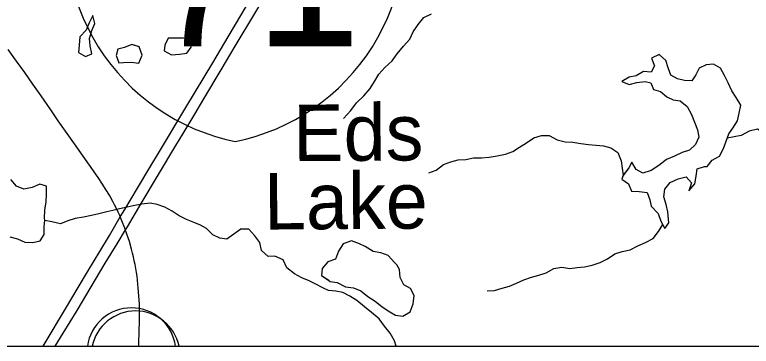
# Model space of a CAD drawing. Extents: x 0 to 34, y 0 to 22.
# Drawn here: x 5.585 to 6.202, y 14.1 to 14.378 of the extents above; entities that cross this region are included whole.
import ezdxf

# ---------------------------------------------------------------- set-up
doc = ezdxf.new("R2010")
doc.units = 0
for name, color, linetype in [('GM_X_Interstate_Route', 7, 'Continuous'), ('GM_X_Interstate_Shield', 7, 'Continuous'), ('GM_X_Minor_Lake', 7, 'Continuous'), ('GM_X_Minor_Lake_Text', 7, 'Continuous'), ('GM_X_Minor_River', 7, 'Continuous'), ('GM_X_Rail_Line_Text', 7, 'Continuous'), ('GM_X_State_Route', 7, 'Continuous'), ('GM_X_Unincorporated_Location', 7, 'Continuous'), ('SH_Cut_Line', 7, 'Continuous'), ('SH_Data', 7, 'Continuous')]:
    doc.layers.add(name, color=color, linetype=linetype)

msp = doc.modelspace()

# ---------------------------------------------------------------- linework, layer by layer
at = {"layer": 'GM_X_Interstate_Route'}
for points in [[(5.67798, 14.19854), (5.67906, 14.20032), (5.69065, 14.21987), (5.71973, 14.26847), (5.72596, 14.27855), (5.73562, 14.29475), (5.7432, 14.30742), (5.75774, 14.33192), (5.76957, 14.35166), (5.80249, 14.40669), (5.808, 14.41604), (5.84195, 14.47264), (5.85026, 14.48655), (5.86397, 14.5094), (5.86958, 14.51854), (5.8945, 14.56039), (5.90385, 14.57596), (5.923, 14.60926), (5.9241, 14.61096)], [(5.60839, 14.1), (5.60927, 14.10147), (5.6281, 14.13291), (5.63695, 14.14778), (5.64664, 14.16387), (5.65605, 14.17956), (5.66403, 14.19295), (5.67316, 14.20845), (5.67689, 14.21479), (5.68766, 14.23262), (5.69708, 14.24845), (5.70698, 14.26485), (5.72812, 14.30025), (5.75058, 14.33766), (5.75982, 14.35336), (5.77875, 14.38497)], [(5.61864, 14.1), (5.6254, 14.111), (5.63703, 14.13011), (5.66057, 14.16971), (5.6704, 14.18605), (5.67744, 14.19766), (5.67798, 14.19854)]]:
    msp.add_lwpolyline(points, dxfattribs=at)
at = {"layer": 'GM_X_Interstate_Shield'}
for centre, start, end in [((5.80508, 14.44572), 165.80665, 258.46304), ((5.73406, 14.44572), 281.53696, 14.19335)]:
    msp.add_arc(centre, 0.17756, start, end, dxfattribs=at)
at = {"layer": 'GM_X_Minor_Lake'}
for points in [[(5.65015, 14.37749), (5.647, 14.37138), (5.64461, 14.36528), (5.63918, 14.35952), (5.63869, 14.35268), (5.6382, 14.34642)], [(5.6382, 14.34642), (5.64412, 14.34307), (5.6494, 14.34542), (5.648, 14.35204), (5.64735, 14.3581), (5.64936, 14.36496), (5.65194, 14.37087), (5.65005, 14.37738)], [(5.6382, 14.34642), (5.64412, 14.34307), (5.6494, 14.34542), (5.648, 14.35204), (5.64735, 14.3581), (5.64936, 14.36496), (5.65194, 14.37087), (5.65007, 14.37733)], [(5.65007, 14.37733), (5.647, 14.37138), (5.64461, 14.36528), (5.63918, 14.35952), (5.63869, 14.35268), (5.6382, 14.34642)], [(5.68905, 14.35108), (5.68289, 14.35305), (5.67666, 14.3505), (5.67098, 14.34929), (5.66972, 14.34397), (5.67188, 14.33773)], [(5.68917, 14.35104), (5.68289, 14.35305), (5.67666, 14.3505), (5.67098, 14.34929), (5.66972, 14.34397), (5.67188, 14.33773)], [(5.73211, 14.3571), (5.72607, 14.35834), (5.71962, 14.35844), (5.71336, 14.35837), (5.7104, 14.35264), (5.70989, 14.34789)], [(5.73216, 14.35709), (5.72607, 14.35834), (5.71962, 14.35844), (5.71336, 14.35837), (5.7104, 14.35264), (5.70989, 14.34789)], [(5.70989, 14.34789), (5.716, 14.34455), (5.72282, 14.34502), (5.72888, 14.34585), (5.73261, 14.35102), (5.73211, 14.3571)], [(5.70989, 14.34789), (5.716, 14.34455), (5.72282, 14.34502), (5.72888, 14.34585), (5.73261, 14.35102), (5.73212, 14.35702)], [(5.67188, 14.33773), (5.67586, 14.33797), (5.68231, 14.33824), (5.68877, 14.33757), (5.69153, 14.34424), (5.68901, 14.35117)], [(5.67188, 14.33773), (5.67586, 14.33797), (5.68231, 14.33824), (5.68877, 14.33757), (5.69153, 14.34424), (5.68905, 14.35108)], [(6.16277, 14.25079), (6.16504, 14.2508), (6.16918, 14.25613), (6.17542, 14.25957), (6.17861, 14.26584), (6.18085, 14.27191), (6.18329, 14.27818), (6.18649, 14.28293), (6.19044, 14.28902), (6.19193, 14.29547), (6.19323, 14.3023), (6.18941, 14.30854), (6.18579, 14.31421), (6.18274, 14.32084), (6.17949, 14.32708), (6.17625, 14.33332), (6.17037, 14.33652), (6.16431, 14.33611), (6.15826, 14.33324), (6.15545, 14.32754), (6.15206, 14.32278), (6.146, 14.32295), (6.14013, 14.32425), (6.13444, 14.32726), (6.13233, 14.3335), (6.13041, 14.33975), (6.12471, 14.34485), (6.11847, 14.34179), (6.12077, 14.33535), (6.11814, 14.32984), (6.11171, 14.33038), (6.10547, 14.32694), (6.09961, 14.32559), (6.09338, 14.32196), (6.09963, 14.31952), (6.10606, 14.32126), (6.11306, 14.32204), (6.1178, 14.32093), (6.1201, 14.31525), (6.12578, 14.31357), (6.1311, 14.30923), (6.13641, 14.3066), (6.14247, 14.30587), (6.14817, 14.30116), (6.1518, 14.29454), (6.15447, 14.2881), (6.15696, 14.28148), (6.15812, 14.27542), (6.15512, 14.26915), (6.15022, 14.26439), (6.14398, 14.26265), (6.13755, 14.25959), (6.13094, 14.25672), (6.12452, 14.25176), (6.1181, 14.24737), (6.11111, 14.24525), (6.10561, 14.24826), (6.10179, 14.25431), (6.09935, 14.24956), (6.09474, 14.24339)], [(6.16277, 14.25079), (6.16504, 14.2508), (6.16918, 14.25613), (6.17542, 14.25957), (6.17861, 14.26584), (6.18085, 14.27191), (6.18329, 14.27818), (6.18649, 14.28293), (6.19044, 14.28902), (6.19193, 14.29547), (6.19323, 14.3023), (6.18941, 14.30854), (6.18579, 14.31421), (6.18274, 14.32084), (6.17949, 14.32708), (6.17625, 14.33332), (6.17037, 14.33652), (6.16431, 14.33611), (6.15826, 14.33324), (6.15545, 14.32754), (6.15206, 14.32278), (6.146, 14.32295), (6.14013, 14.32425), (6.13444, 14.32726), (6.13233, 14.3335), (6.13041, 14.33975), (6.12471, 14.34485), (6.11847, 14.34179), (6.12077, 14.33535), (6.11814, 14.32984), (6.11171, 14.33038), (6.10547, 14.32694), (6.09961, 14.32559), (6.09338, 14.32196), (6.09963, 14.31952), (6.10606, 14.32126), (6.11306, 14.32204), (6.1178, 14.32093), (6.1201, 14.31525), (6.12578, 14.31357), (6.1311, 14.30923), (6.13641, 14.3066), (6.14247, 14.30587), (6.14817, 14.30116), (6.1518, 14.29454), (6.15447, 14.2881), (6.15696, 14.28148), (6.15812, 14.27542), (6.15512, 14.26915), (6.15022, 14.26439), (6.14398, 14.26265), (6.13755, 14.25959), (6.13094, 14.25672), (6.12452, 14.25176), (6.1181, 14.24737), (6.11111, 14.24525), (6.10561, 14.24826), (6.10179, 14.25431), (6.09935, 14.24956), (6.09469, 14.24332)], [(6.09474, 14.24339), (6.09352, 14.24025), (6.09922, 14.23629), (6.1017, 14.23024), (6.10795, 14.22969), (6.11477, 14.22897), (6.11707, 14.22272), (6.11823, 14.21742), (6.12393, 14.21137), (6.12623, 14.20494), (6.12966, 14.1987), (6.13286, 14.20364), (6.13207, 14.21274), (6.13072, 14.2188), (6.12861, 14.22543), (6.12953, 14.23187), (6.13405, 14.23739), (6.14066, 14.24046), (6.14747, 14.242), (6.15184, 14.23709), (6.1496, 14.23026), (6.15469, 14.23635), (6.1558, 14.2428), (6.15653, 14.24887), (6.16277, 14.25079)], [(6.09471, 14.24332), (6.09352, 14.24025), (6.09922, 14.23629), (6.1017, 14.23024), (6.10795, 14.22969), (6.11477, 14.22897), (6.11707, 14.22272), (6.11823, 14.21742), (6.12393, 14.21137), (6.12623, 14.20494), (6.12966, 14.1987), (6.13286, 14.20364), (6.13207, 14.21274), (6.13072, 14.2188), (6.12861, 14.22543), (6.12953, 14.23187), (6.13405, 14.23739), (6.14066, 14.24046), (6.14747, 14.242), (6.15184, 14.23709), (6.1496, 14.23026), (6.15469, 14.23635), (6.1558, 14.2428), (6.15653, 14.24887), (6.16277, 14.25079)], [(5.60989, 14.20583), (5.60974, 14.20737), (5.60984, 14.2142), (5.6109, 14.22104), (5.61139, 14.2275), (5.61131, 14.23433), (5.60559, 14.23596), (5.59918, 14.23304), (5.59237, 14.23181), (5.58608, 14.2342), (5.58145, 14.24002)], [(5.58071, 14.19183), (5.587, 14.19001), (5.5931, 14.18743), (5.59974, 14.18713), (5.60599, 14.18835), (5.60933, 14.19389), (5.60945, 14.20016), (5.60989, 14.20587)], [(5.58071, 14.19183), (5.587, 14.19001), (5.5931, 14.18743), (5.59974, 14.18713), (5.60599, 14.18835), (5.60933, 14.19389), (5.60945, 14.20016), (5.60989, 14.20583)], [(5.90492, 14.16823), (5.90299, 14.17028), (5.89757, 14.17606), (5.89165, 14.17842), (5.88518, 14.17943), (5.87846, 14.18367), (5.87368, 14.18586), (5.8668, 14.18858), (5.86003, 14.18579), (5.85597, 14.17964), (5.85343, 14.17315), (5.84703, 14.17094), (5.84239, 14.16535), (5.84174, 14.15946), (5.84789, 14.15515)], [(5.90492, 14.16823), (5.90299, 14.17028), (5.89757, 14.17606), (5.89165, 14.17842), (5.88518, 14.17943), (5.87846, 14.18367), (5.87368, 14.18586), (5.8668, 14.18858), (5.86003, 14.18579), (5.85597, 14.17964), (5.85343, 14.17315), (5.84703, 14.17094), (5.84239, 14.16535), (5.84174, 14.15946), (5.84789, 14.1554)], [(5.84789, 14.15515), (5.84893, 14.15441), (5.85494, 14.15363), (5.86184, 14.14978), (5.86849, 14.14914), (5.8748, 14.14642), (5.88057, 14.14178), (5.88691, 14.13773), (5.89268, 14.13309), (5.89902, 14.12884), (5.90381, 14.12609), (5.91009, 14.12526), (5.91609, 14.12898), (5.91862, 14.13566), (5.91944, 14.14251), (5.91648, 14.14834), (5.91073, 14.15164), (5.90778, 14.15766), (5.90708, 14.16429), (5.90492, 14.16823)]]:
    msp.add_lwpolyline(points, dxfattribs=at)
at = {"layer": 'GM_X_Minor_River'}
for points in [[(5.86027, 14.29117), (5.8663, 14.29764), (5.871, 14.3041), (5.87723, 14.31001), (5.8825, 14.3161), (5.88608, 14.32218), (5.88984, 14.32826), (5.89493, 14.33378), (5.90115, 14.3395), (5.90529, 14.34539), (5.91057, 14.35167), (5.91584, 14.35757), (5.91866, 14.36365), (5.9228, 14.36993), (5.92751, 14.37564), (5.93411, 14.37889)], [(6.28076, 14.27376), (6.28005, 14.27348), (6.274, 14.27232), (6.26795, 14.26983), (6.26266, 14.26677), (6.25734, 14.27111), (6.25164, 14.2762), (6.24521, 14.2739), (6.23934, 14.27501), (6.2329, 14.27707), (6.22702, 14.27875), (6.22021, 14.27815), (6.21339, 14.27831), (6.20713, 14.28208), (6.20032, 14.28034), (6.19352, 14.2769), (6.1819, 14.2746)], [(5.93164, 14.24541), (5.93787, 14.24771), (5.9441, 14.25248), (5.95015, 14.25478), (5.9562, 14.25652), (5.96283, 14.25673), (5.96907, 14.25809), (5.97589, 14.25793), (5.98232, 14.25853), (5.98913, 14.25969), (5.99594, 14.26105), (6.00218, 14.26335), (6.00784, 14.26698), (6.0137, 14.27061), (6.01974, 14.27481), (6.02617, 14.27673), (6.0326, 14.27676), (6.03943, 14.27319), (6.04588, 14.27151), (6.05231, 14.27116), (6.05913, 14.27005), (6.06557, 14.26932), (6.07201, 14.26878), (6.07826, 14.26824), (6.08433, 14.26656), (6.09021, 14.26241), (6.09289, 14.2556), (6.09469, 14.24332)], [(5.90436, 14.1), (5.90292, 14.1045), (5.89946, 14.11093), (5.89449, 14.11678), (5.89009, 14.12301), (5.8838, 14.12828), (5.8777, 14.13298), (5.8714, 14.13844), (5.8655, 14.142), (5.85979, 14.145), (5.85371, 14.1461), (5.84764, 14.14681), (5.84289, 14.14906), (5.83661, 14.15224), (5.83147, 14.15486), (5.82519, 14.15729), (5.8191, 14.16085), (5.81262, 14.16593), (5.80954, 14.17255), (5.80269, 14.17554), (5.79701, 14.17531), (5.79148, 14.1802), (5.7901, 14.18702), (5.78589, 14.1925), (5.78093, 14.19816), (5.7741, 14.19811), (5.76825, 14.19409), (5.7624, 14.18987), (5.7567, 14.19059), (5.75062, 14.1934), (5.74527, 14.19886), (5.74051, 14.20168), (5.73576, 14.20354), (5.72872, 14.20634), (5.72263, 14.20933), (5.71654, 14.21328), (5.71045, 14.21665), (5.70398, 14.21888), (5.6981, 14.21998), (5.69128, 14.21918), (5.68408, 14.2178), (5.67897, 14.21663), (5.67253, 14.21525), (5.66685, 14.21389), (5.66193, 14.21272), (5.65511, 14.21115), (5.64905, 14.20959), (5.64242, 14.20822), (5.63522, 14.20722), (5.62917, 14.2051), (5.62293, 14.20259), (5.6159, 14.20444), (5.60987, 14.20563)], [(5.9807, 14.14648), (5.98676, 14.14669), (5.99318, 14.14862), (5.99923, 14.15054), (6.00528, 14.15303), (6.01133, 14.15571), (6.01776, 14.15783), (6.02381, 14.15975), (6.03005, 14.16167), (6.03647, 14.1653), (6.04309, 14.16647), (6.04991, 14.16517), (6.05615, 14.16596), (6.06221, 14.16674), (6.06864, 14.1681), (6.07526, 14.1704), (6.08149, 14.17346), (6.08772, 14.17766), (6.09377, 14.17958), (6.10039, 14.18094), (6.10681, 14.18419), (6.11324, 14.18706), (6.11966, 14.1905), (6.12418, 14.19621), (6.12781, 14.20206)]]:
    msp.add_lwpolyline(points, dxfattribs=at)
at = {"layer": 'GM_X_Rail_Line_Text'}
msp.add_lwpolyline([(4.29894, 14.1), (6.7466, 14.1), (6.74627, 14.36613), (6.74627, 14.37116), (6.74201, 15.01654)], dxfattribs=at)
at = {"layer": 'GM_X_State_Route'}
msp.add_lwpolyline([(5.68858, 14.1), (5.68875, 14.10549), (5.68888, 14.10919), (5.68916, 14.12418), (5.68922, 14.1356), (5.68827, 14.14886), (5.68796, 14.15215), (5.68759, 14.15543), (5.68717, 14.15871), (5.68669, 14.16198), (5.68614, 14.16524), (5.68555, 14.16849), (5.6849, 14.17173), (5.68419, 14.17495), (5.68342, 14.17817), (5.6826, 14.18137), (5.68076, 14.18784), (5.67977, 14.191), (5.67873, 14.19414), (5.67792, 14.19644), (5.67744, 14.19766), (5.674, 14.20652), (5.67316, 14.20845), (5.67268, 14.20956), (5.67131, 14.21258), (5.66989, 14.21557), (5.66842, 14.21854), (5.66689, 14.22148), (5.66439, 14.22606), (5.66207, 14.22991), (5.66138, 14.23106), (5.6583, 14.23601), (5.65467, 14.24159), (5.6348, 14.26986), (5.62102, 14.28923), (5.61483, 14.29841), (5.60697, 14.31005), (5.59996, 14.31989), (5.59301, 14.32965), (5.58616, 14.33927), (5.57931, 14.34888)], dxfattribs=at)
at = {"layer": 'GM_X_Unincorporated_Location'}
for p, q in [((5.64567, 14.1), (5.71941, 14.1)), ((5.64956, 14.1), (5.72239, 14.1))]:
    msp.add_line(p, q, dxfattribs=at)
for centre, start, end in [((5.68254, 14.09506), 7.6289, 172.3711), ((5.68598, 14.09241), 11.77455, 168.22545)]:
    msp.add_arc(centre, 0.0372, start, end, dxfattribs=at)
at = {"layer": 'SH_Cut_Line'}
msp.add_lwpolyline([(2.1, 20.39416), (2.1, 14.1), (8.9, 14.1)], dxfattribs=at)
at = {"layer": 'SH_Data'}
msp.add_line((2.1, 14.1), (8.9, 14.1), dxfattribs=at)

# ---------------------------------------------------------------- texts
at = {"layer": 'GM_X_Interstate_Shield'}
msp.add_text('71', height=0.118371, dxfattribs=at).set_placement((5.69834, 14.35166))
at = {"layer": 'GM_X_Minor_Lake_Text'}
for s, rotation, p in [('Eds', 0.3661, (5.81817, 14.25525)), (' Lake', 0.36589, (5.77609, 14.19776))]:
    msp.add_text(s, height=0.047368, rotation=rotation, dxfattribs=at).set_placement(p)

doc.saveas('drawing.dxf')
